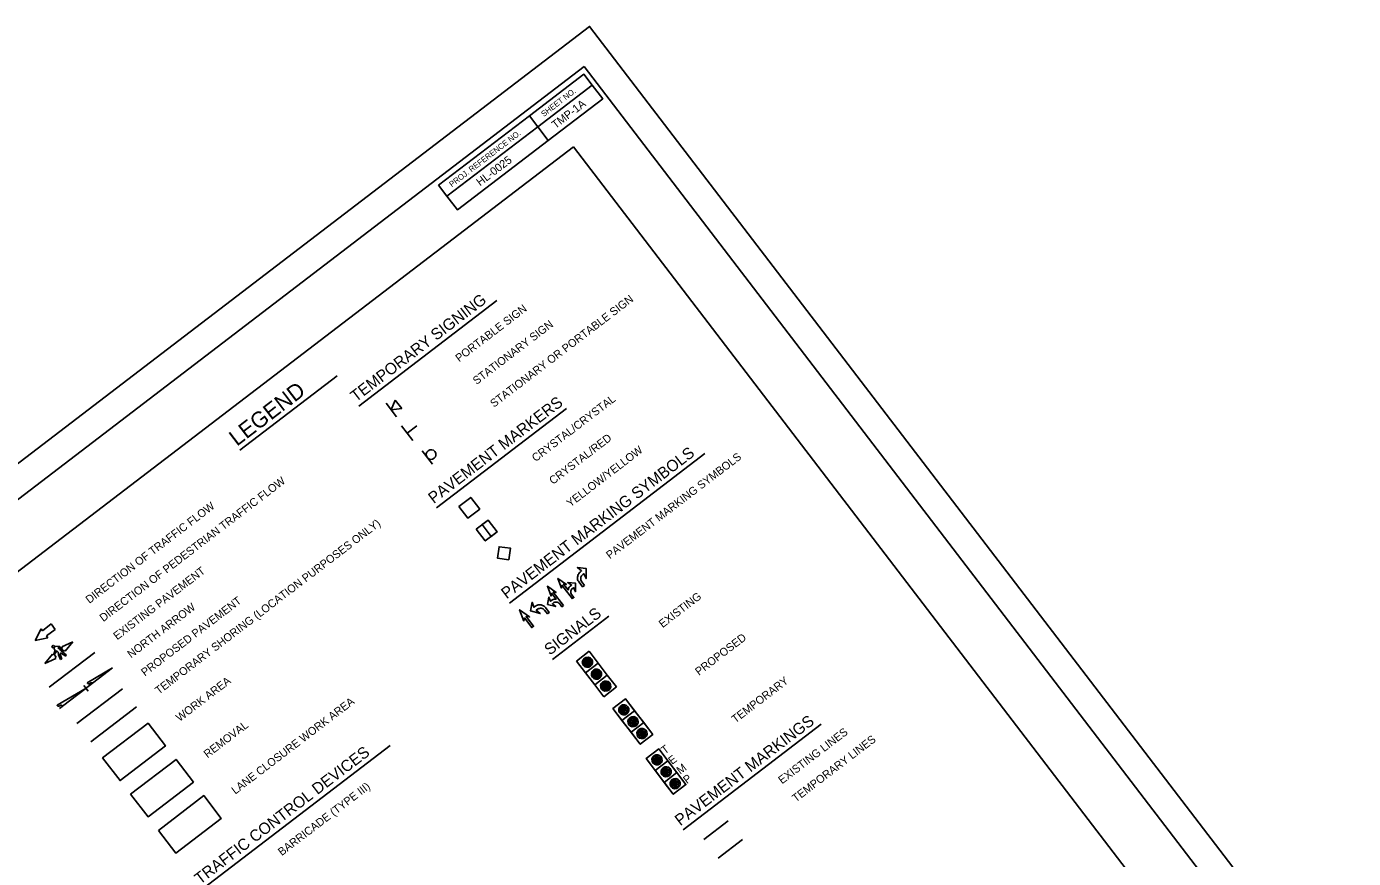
# Model space of a CAD drawing. Extents: x -642 to 2005, y -4412 to 1950.
# Drawn here: x 844 to 2005, y 1222 to 1950 of the extents above; entities that cross this region are included whole.
import ezdxf

# ---------------------------------------------------------------- set-up
doc = ezdxf.new("R2010")
doc.units = 0
for name, color, linetype in [('DEV BORDER CELL', 7, 'Continuous'), ('Gray Area Fill Shapes', 7, 'Continuous'), ('Scratch_Level_0', 7, 'Continuous'), ('Sheet Plot Border Outside CELL', 7, 'Continuous')]:
    doc.layers.add(name, color=color, linetype=linetype)

msp = doc.modelspace()

# ---------------------------------------------------------------- linework, layer by layer
at = {"layer": 'DEV BORDER CELL'}
for p, q in [((1291, 1861.8), (1338.6, 1898.3)), ((1134.4, 1617.4), (1255.3, 1709.9)), ((1030.3, 1578.7), (1115.6, 1643.9)), ((1158.4, 1619.9), (1167.4, 1608.1)), ((1162.8, 1614.1), (1166.4, 1622.7)), ((1172, 1615.3), (1162.8, 1614.1)), ((1166.4, 1622.7), (1172, 1615.3)), ((1202.5, 1528.4), (1316.2, 1615.4)), ((1171.9, 1600.2), (1181.8, 1587.3)), ((1176.9, 1593.7), (1185.2, 1600.1)), ((1189.8, 1578.3), (1198.9, 1566.6)), ((1266.2, 1445), (1437.2, 1575.8)), ((1303.9, 1395.7), (1353.3, 1433.5)), ((856.6, 1422.4), (851.3, 1412.2)), ((857.8, 1420.8), (856.6, 1422.4)), ((865.4, 1426.7), (857.8, 1420.8)), ((861.3, 1416.2), (868.9, 1422)), ((862.5, 1414.6), (861.3, 1416.2)), ((868.9, 1422), (865.4, 1426.7)), ((851.3, 1412.2), (862.5, 1414.6)), ((869.5, 1407.1), (872.4, 1407.4)), ((872, 1406.3), (871.3, 1406)), ((873.9, 1404.2), (872, 1406.3)), ((872.4, 1407.4), (874.5, 1404.7)), ((874.5, 1404.7), (873.9, 1404.2)), ((875.2, 1405.9), (874.5, 1405.3)), ((874.5, 1405.3), (876.2, 1403)), ((884.3, 1411), (874.6, 1406.6)), ((874.6, 1406.6), (875.2, 1405.9)), ((877.6, 1402.8), (884.3, 1411)), ((866.5, 1400.4), (859.7, 1392.2)), ((859.7, 1392.2), (869.4, 1396.5)), ((863.6, 1371.3), (903.5, 1401.8)), ((867.1, 1399.6), (866.5, 1400.4)), ((867.8, 1400.2), (867.1, 1399.6)), ((867.8, 1400.6), (868.8, 1403.4)), ((868.4, 1400.4), (867.8, 1400.6)), ((869.6, 1397.9), (867.8, 1400.2)), ((868.8, 1403.4), (868.3, 1404.3)), ((869.8, 1402.4), (868.4, 1400.4)), ((868.8, 1397.3), (869.6, 1397.9)), ((869.4, 1396.5), (868.8, 1397.3)), ((870, 1403.4), (869.8, 1402.4)), ((871.8, 1399.6), (871.4, 1402.1)), ((873.4, 1395.7), (871.8, 1399.6)), ((873.4, 1401.4), (873.3, 1400)), ((873.3, 1400), (874.7, 1396.2)), ((878.2, 1398.5), (873.4, 1401.4)), ((874.7, 1396.2), (873.4, 1395.7)), ((874.2, 1403.1), (878.5, 1399.6)), ((876.2, 1403), (877, 1403.6)), ((877, 1403.6), (877.6, 1402.8)), ((878.5, 1399.6), (878.2, 1398.5)), ((1324.9, 1394.3), (1335.9, 1402.8)), ((1332.8, 1383.9), (1324.9, 1394.3)), ((1330, 1393), (1330.3, 1394.7)), ((1330, 1393.6), (1338.8, 1392.4)), ((1330.2, 1394.5), (1338.9, 1393.4)), ((1330.6, 1395.5), (1338.8, 1394.5)), ((1330.7, 1390.8), (1331.5, 1396.6)), ((1331.4, 1396.4), (1338.3, 1395.5)), ((1331.6, 1389.8), (1332.6, 1397.3)), ((1332.6, 1389.2), (1333.7, 1397.6)), ((1332.6, 1397.3), (1337.4, 1396.7)), ((1333.5, 1388.9), (1334.7, 1397.7)), ((1334.5, 1388.8), (1335.7, 1397.5)), ((1335.6, 1388.9), (1336.7, 1397.1)), ((1335.9, 1402.8), (1343.9, 1392.4)), ((1336.6, 1389.4), (1337.6, 1396.5)), ((1337.8, 1390.3), (1338.4, 1395.3)), ((872.6, 1352.7), (919.1, 1388.2)), ((896.9, 1375.2), (919.1, 1388.2)), ((919.1, 1388.2), (901.4, 1374.8)), ((1330.1, 1392.5), (1338.5, 1391.4)), ((1330.4, 1391.5), (1338, 1390.5)), ((1331, 1390.4), (1337, 1389.6)), ((1332.7, 1389.2), (1335.1, 1388.9)), ((1332.8, 1383.9), (1343.9, 1392.4)), ((1340.8, 1373.5), (1332.8, 1383.9)), ((1338, 1383.4), (1346.8, 1382.2)), ((1338, 1382.4), (1346.6, 1381.3)), ((1338.1, 1381.9), (1338.5, 1384.9)), ((1338.2, 1381.3), (1346.1, 1380.3)), ((1338.3, 1384.4), (1346.9, 1383.2)), ((1338.7, 1385.3), (1346.7, 1384.3)), ((1338.9, 1380.2), (1339.7, 1386.3)), ((1339.5, 1386.2), (1346.1, 1385.4)), ((1339.8, 1379.3), (1340.8, 1387)), ((1340.7, 1378.7), (1341.9, 1387.3)), ((1351.8, 1382), (1340.8, 1373.5)), ((1341, 1387), (1345, 1386.5)), ((1341.7, 1378.5), (1342.9, 1387.3)), ((1342.7, 1378.4), (1343.9, 1387.1)), ((1343.7, 1378.6), (1344.8, 1386.6)), ((1343.9, 1392.4), (1351.8, 1382)), ((1344.8, 1379.1), (1345.7, 1385.9)), ((1345.9, 1380.1), (1346.6, 1384.6)), ((1351.8, 1382), (1359.8, 1371.6)), ((895.9, 1370.5), (870.5, 1355.6)), ((875.4, 1354.8), (895.9, 1370.5)), ((887.9, 1339.5), (927.8, 1370)), ((894, 1373), (897.8, 1368)), ((1338.8, 1380.2), (1345.2, 1379.4)), ((1340.1, 1379.1), (1343.7, 1378.6)), ((1348.8, 1363.1), (1340.8, 1373.5)), ((1346, 1373.1), (1354.8, 1372)), ((1346, 1372.1), (1354.6, 1371)), ((1346.1, 1371.1), (1354.1, 1370.1)), ((1346.3, 1374.1), (1354.8, 1373)), ((1346.6, 1370.1), (1347.3, 1375.6)), ((1346.7, 1370), (1353.4, 1369.1)), ((1346.8, 1375), (1354.6, 1374)), ((1347.4, 1369.1), (1348.4, 1376.4)), ((1347.7, 1375.9), (1354, 1375.1)), ((1348.4, 1368.5), (1349.5, 1376.8)), ((1359.8, 1371.6), (1348.8, 1363.1)), ((1349.3, 1368.1), (1350.5, 1376.9)), ((1349.3, 1376.8), (1352.6, 1376.3)), ((1350.3, 1368), (1351.5, 1376.8)), ((1351.4, 1368.1), (1352.5, 1376.4)), ((1352.4, 1368.5), (1353.4, 1375.8)), ((1353.5, 1369.3), (1354.3, 1374.7)), ((1347.7, 1368.9), (1352, 1368.3)), ((900, 1323.6), (939.9, 1354.1)), ((1370.5, 1350.4), (1361.9, 1351.5)), ((1370.7, 1351.9), (1362.1, 1353)), ((1369.8, 1349), (1362.2, 1349.9)), ((1362.7, 1349), (1363.6, 1355.1)), ((1370.4, 1353.4), (1362.9, 1354.4)), ((1368.2, 1347.6), (1363.4, 1348.3)), ((1364.1, 1347.8), (1365.2, 1355.9)), ((1369, 1355.1), (1364.6, 1355.7)), ((1365.5, 1347.3), (1366.7, 1356)), ((1367, 1347.3), (1368.2, 1355.6)), ((1368.6, 1347.9), (1369.6, 1354.6)), ((1370.5, 1350.3), (1370.7, 1352.1)), ((1378.5, 1340), (1369.9, 1341.1)), ((1378.7, 1341.5), (1370.1, 1342.6)), ((1377.8, 1338.5), (1370.2, 1339.5)), ((1370.7, 1338.6), (1371.5, 1344.7)), ((1378.3, 1343), (1370.8, 1344)), ((1376.2, 1337.2), (1371.4, 1337.9)), ((1372.1, 1337.4), (1373.1, 1345.5)), ((1377, 1344.7), (1372.6, 1345.3)), ((1373.5, 1336.8), (1374.7, 1345.6)), ((1375, 1336.9), (1376.2, 1345.2)), ((1376.6, 1337.5), (1377.5, 1344.2)), ((1378.5, 1339.9), (1378.7, 1341.6)), ((1380, 1327), (1381.1, 1335.1)), ((1385, 1334.3), (1380.6, 1334.9)), ((1381.4, 1326.4), (1382.7, 1335.2)), ((1418.1, 1246.5), (1539, 1338.9)), ((1386.5, 1329.6), (1377.8, 1330.7)), ((1386.7, 1331.1), (1378, 1332.2)), ((1385.7, 1328.1), (1378.1, 1329.1)), ((1378.6, 1328.2), (1379.5, 1334.2)), ((1386.3, 1332.6), (1378.8, 1333.6)), ((1384.1, 1326.8), (1379.3, 1327.5)), ((1383, 1326.5), (1384.1, 1334.8)), ((1384.5, 1327.1), (1385.5, 1333.8)), ((1386.4, 1329.5), (1386.7, 1331.2)), ((998.1, 1195.3), (1161.9, 1320.5)), ((1393.1, 1304), (1394.2, 1312.1)), ((1394.5, 1303.5), (1395.7, 1312.2)), ((1396, 1303.5), (1397.2, 1311.8)), ((1399.5, 1306.6), (1390.9, 1307.7)), ((1399.7, 1308.1), (1391.1, 1309.2)), ((1398.8, 1305.2), (1391.2, 1306.1)), ((1391.7, 1305.2), (1392.6, 1311.3)), ((1399.4, 1309.6), (1391.9, 1310.6)), ((1397.2, 1303.8), (1392.4, 1304.5)), ((1397.6, 1304.1), (1398.6, 1310.8)), ((1399.7, 1294.8), (1400.5, 1300.9)), ((1407.3, 1299.2), (1399.8, 1300.2)), ((1401.1, 1293.6), (1402.1, 1301.7)), ((1402.5, 1293.1), (1403.7, 1301.8)), ((1404, 1293.1), (1405.2, 1301.4)), ((1405.6, 1293.7), (1406.5, 1300.4)), ((1407.5, 1296.2), (1398.9, 1297.3)), ((1407.7, 1297.7), (1399, 1298.8)), ((1406.8, 1294.8), (1399.2, 1295.7)), ((1405.2, 1293.4), (1400.4, 1294.1)), ((1415.7, 1287.3), (1407, 1288.4)), ((1407.6, 1284.4), (1408.5, 1290.5)), ((1415.3, 1288.8), (1407.8, 1289.8)), ((1409, 1283.2), (1410.1, 1291.3)), ((1410.4, 1282.6), (1411.6, 1291.4)), ((1411.9, 1282.7), (1413.1, 1291)), ((1413.5, 1283.3), (1414.5, 1290)), ((1415.5, 1285.8), (1406.8, 1286.9)), ((1414.7, 1284.3), (1407.1, 1285.3)), ((1413.1, 1283), (1408.3, 1283.7)), ((998.9, 1276.5), (959.2, 1246.1)), ((1014.1, 1256.6), (998.9, 1276.5)), ((974.4, 1226.2), (1014.1, 1256.6)), ((1436.2, 1238.2), (1457.5, 1254.4)), ((959.2, 1246.1), (974.4, 1226.2)), ((1448.8, 1221.7), (1470.1, 1238))]:
    msp.add_line(p, q, dxfattribs=at)
for points in [[(1331.7, 1914.5), (140.1, 1003.4), (777.9, 169.3), (1969.5, 1080.4)], [(1291, 1861.8), (1338.6, 1898.3), (1331.4, 1907.8), (1283.7, 1871.4)], [(1291, 1861.8), (1338.6, 1898.3), (1347.8, 1886.4), (1300.1, 1849.9)], [(1204.3, 1810.6), (1283.7, 1871.4), (1291, 1861.8), (1211.5, 1801.1)], [(1291, 1861.8), (1211.5, 1801.1), (1220.7, 1789.2), (1300.1, 1849.9)], [(1242.4, 1513.7), (1247.5, 1517.6), (1255.4, 1507.3), (1250.3, 1503.4)], [(1265.8, 1483), (1267.2, 1493), (1257.2, 1494.3), (1255.9, 1484.3)], [(1265.8, 1483), (1267.2, 1493), (1257.2, 1494.3), (1255.9, 1484.3)], [(1265.8, 1483), (1255.9, 1484.3), (1257.2, 1494.3), (1267.2, 1493)], [(1331.8, 1460.5), (1330.2, 1459.3), (1327.1, 1463.4), (1326.6, 1464.2), (1326.2, 1464.9), (1325.9, 1465.6), (1325.8, 1466.4), (1325.8, 1467), (1325.8, 1467.8), (1326, 1468.5), (1326.1, 1469.2), (1326.5, 1470.1), (1326.8, 1470.7), (1327.3, 1471.4), (1328.2, 1472.2), (1329.4, 1473.2), (1325.7, 1476), (1333.3, 1475.3), (1333.3, 1466.5), (1331.4, 1470.7), (1330.3, 1469.9), (1329.8, 1469.4), (1329.3, 1468.8), (1329, 1468.3), (1328.7, 1467.6), (1328.6, 1467), (1328.6, 1466.1), (1328.7, 1465.3), (1329, 1464.5), (1329.5, 1463.6)], [(1321.3, 1448.8), (1312.2, 1460.6), (1311.8, 1458.1), (1308.6, 1466.6), (1316.1, 1461.4), (1313.6, 1461.6), (1317.5, 1456.5), (1317.8, 1457.4), (1318, 1458.1), (1318.5, 1458.8), (1318.9, 1459.3), (1319.4, 1459.8), (1320.6, 1460.7), (1317.3, 1463), (1323.9, 1462.5), (1323.9, 1454.9), (1322.2, 1458.5), (1321.4, 1457.8), (1320.9, 1457.4), (1320.4, 1456.9), (1320.2, 1456.3), (1319.9, 1455.7), (1319.8, 1454.8), (1319.9, 1454), (1320.2, 1453.2), (1320.6, 1452.4), (1322.6, 1449.8)], [(1313.5, 1442.8), (1304.5, 1454.6), (1307, 1454.4), (1299.5, 1459.7), (1302.7, 1451.1), (1303.1, 1453.6), (1307, 1448.4), (1306, 1448.5), (1305.3, 1448.4), (1304.5, 1448.1), (1304, 1447.9), (1303.3, 1447.5), (1302.2, 1446.6), (1300.7, 1450.3), (1299.6, 1443.9), (1306.8, 1441.9), (1303.8, 1444.4), (1304.7, 1445.1), (1305.2, 1445.5), (1305.9, 1445.7), (1306.5, 1445.8), (1307.2, 1445.9), (1308, 1445.8), (1308.8, 1445.5), (1309.5, 1445), (1310.2, 1444.4), (1312.1, 1441.8)], [(1299.4, 1435.7), (1301, 1436.9), (1297.8, 1441), (1297.2, 1441.8), (1296.7, 1442.3), (1296, 1442.7), (1295.3, 1443), (1294.7, 1443.2), (1293.9, 1443.4), (1293.2, 1443.5), (1292.4, 1443.5), (1291.5, 1443.4), (1290.9, 1443.2), (1290, 1442.9), (1289, 1442.3), (1287.7, 1441.3), (1286.1, 1445.7), (1284.7, 1438.1), (1293.2, 1435.8), (1289.7, 1438.8), (1290.7, 1439.6), (1291.3, 1440), (1292, 1440.3), (1292.6, 1440.4), (1293.4, 1440.5), (1294, 1440.5), (1294.8, 1440.3), (1295.6, 1439.9), (1296.3, 1439.5), (1297, 1438.8)], [(1278.8, 1429.1), (1279.3, 1432), (1285.7, 1423.5), (1287.3, 1424.7), (1280.8, 1433.2), (1283.8, 1432.9), (1275.1, 1439.1)], [(1356.7, 1352.7), (1367.8, 1361.2), (1391.6, 1330), (1380.6, 1321.5)], [(1364.7, 1342.3), (1375.7, 1350.8), (1367.8, 1361.2), (1356.7, 1352.7)], [(1372.6, 1331.9), (1383.7, 1340.4), (1375.7, 1350.8), (1364.7, 1342.3)], [(910.4, 1309.5), (950.1, 1339.9), (965.3, 1320), (925.6, 1289.6)], [(1380.6, 1321.5), (1391.6, 1330), (1383.7, 1340.4), (1372.6, 1331.9)], [(1385.7, 1308.9), (1396.8, 1317.4), (1420.6, 1286.2), (1409.6, 1277.7)], [(1393.7, 1298.5), (1404.7, 1307), (1396.8, 1317.4), (1385.7, 1308.9)], [(934.9, 1277.9), (974.6, 1308.2), (989.8, 1288.4), (950.1, 1258)], [(934.9, 1277.9), (974.6, 1308.2), (989.8, 1288.4), (950.1, 1258)], [(934.9, 1277.9), (974.6, 1308.2), (989.8, 1288.4), (950.1, 1258)], [(1401.6, 1288.1), (1412.7, 1296.6), (1404.7, 1307), (1393.7, 1298.5)], [(1409.6, 1277.7), (1420.6, 1286.2), (1412.7, 1296.6), (1401.6, 1288.1)], [(959.2, 1246.1), (998.9, 1276.5), (1014.1, 1256.6), (974.4, 1226.2)]]:
    msp.add_lwpolyline(points, close=True, dxfattribs=at)
for points in [[(1222, 1529.6), (1232.4, 1537.5), (1240.3, 1527.2), (1229.9, 1519.3), (1222, 1529.6)], [(1237.2, 1509.7), (1247.5, 1517.6), (1255.4, 1507.3), (1245.1, 1499.4), (1237.2, 1509.7)]]:
    msp.add_lwpolyline(points, dxfattribs=at)
msp.add_circle((867.2, 1406.9), 1.11, dxfattribs=at)
for centre, radius, start, end in [((1197.7, 1575), 4.28, 220.3871, 217.2203), ((871.2, 1405.8), 3.22, 177.5907, 207.9785), ((868.8, 1405.9), 0.84, 134.3035, 177.5907), ((869.7, 1404.9), 2.19, 96.5687, 134.3035), ((867.1, 1398.8), 8.29, 31.0586, 59.6568), ((867.1, 1398.8), 5.41, 37.711, 57.7902)]:
    msp.add_arc(centre, radius, start, end, dxfattribs=at)
for centre, major_axis in [((1334.5, 1393.2), (3.55, 2.72)), ((1342.4, 1382.8), (3.55, 2.72)), ((1350.4, 1372.4), (3.55, 2.72)), ((1366.3, 1351.6), (3.55, 2.71)), ((1374.3, 1341.2), (3.55, 2.71)), ((1382.2, 1330.8), (3.55, 2.71)), ((1395.3, 1307.8), (3.55, 2.71)), ((1403.3, 1297.4), (3.55, 2.71)), ((1411.2, 1287), (3.55, 2.71))]:
    msp.add_ellipse(centre, major_axis=major_axis, ratio=0.992944, dxfattribs=at)
for points in [[(901.4, 1374.7), (900.8, 1375.9), (897.9, 1373.7), (896.9, 1375.2)], [(870.5, 1355.6), (871.5, 1354.1), (874.4, 1356.2), (875.4, 1354.8)]]:
    msp.add_open_spline(points, degree=2, dxfattribs=at)
at = {"layer": 'Gray Area Fill Shapes'}
msp.add_lwpolyline([(925.6, 1289.6), (965.3, 1320), (950.1, 1339.9), (910.4, 1309.5)], close=True, dxfattribs=at)
at = {"layer": 'Scratch_Level_0'}
msp.add_lwpolyline([(1322.3, 1844.4), (210.2, 994), (787.3, 239.4), (1485.4, 773.2), (1413.6, 867.2), (1827.6, 1183.7)], close=True, dxfattribs=at)
at = {"layer": 'Sheet Plot Border Outside CELL'}
msp.add_lwpolyline([(663.6, 50.4), (2004.5, 1075.8), (1336.4, 1949.6), (-4.5, 924.2)], close=True, dxfattribs=at)

# ---------------------------------------------------------------- texts
at = {"layer": 'DEV BORDER CELL'}
for s, height, rotation, p in [('SHEET NO.', 5, 37.4045, (1296.3, 1870.3)), ('TMP-1A', 7, 37.404, (1306.5, 1859.8)), ('PROJ. REFERENCE NO.', 4.999, 37.4045, (1215.9, 1808.8)), ('HL-0025', 7, 37.404, (1240.6, 1809.6)), ('TEMPORARY SIGNING', 10, 37.4042, (1132, 1620.6)), ('PORTABLE SIGN', 7, 37.4042, (1222.3, 1655.6)), ('STATIONARY OR PORTABLE SIGN', 7, 37.4042, (1252.7, 1615.9)), ('STATIONARY SIGN', 7, 37.4042, (1237.5, 1635.8)), ('LEGEND', 14, 37.404, (1027.8, 1581.8)), ('PAVEMENT MARKERS', 10, 37.4042, (1200, 1531.6)), ('CRYSTAL/CRYSTAL', 7, 37.4042, (1289.1, 1568.3)), ('CRYSTAL/RED', 7, 37.4042, (1304.3, 1548.4)), ('PAVEMENT MARKING SYMBOLS', 10, 37.4042, (1263.8, 1448.2)), ('YELLOW/YELLOW', 7, 37.4042, (1319.5, 1528.6)), ('PAVEMENT MARKING SYMBOLS', 7, 37.4042, (1354.1, 1483.2)), ('DIRECTION OF PEDESTRIAN TRAFFIC FLOW', 7, 37.404, (911, 1428.3)), ('DIRECTION OF TRAFFIC FLOW', 7, 37.404, (898.8, 1444.2)), ('TEMPORARY SHORING (LOCATION PURPOSES ONLY)', 7, 37.404, (959.6, 1364.7)), ('EXISTING PAVEMENT', 7, 37.404, (923.1, 1412.4)), ('PROPOSED PAVEMENT', 7, 37.404, (947.4, 1380.6)), ('EXISTING', 7, 37.4045, (1400.2, 1423)), ('NORTH ARROW', 7, 37.404, (935.3, 1396.5)), ('SIGNALS', 10, 37.4042, (1301.5, 1398.9)), ('PROPOSED', 7, 37.4045, (1432, 1381.3)), ('WORK AREA', 7, 37.404, (977.8, 1340.9)), ('TEMPORARY ', 7, 37.4045, (1463.9, 1339.6)), ('LANE CLOSURE WORK AREA', 7, 37.404, (1026.4, 1277.3)), ('PAVEMENT MARKINGS', 10, 37.4042, (1415.7, 1249.6)), ('REMOVAL', 7, 37.404, (1002.1, 1309.1)), ('EXISTING LINES', 7, 37.4042, (1504.7, 1286.3)), ('TEMPORARY LINES', 7, 37.4042, (1516.8, 1270.4)), ('TRAFFIC CONTROL DEVICES', 10, 37.4042, (995.6, 1198.4)), ('T', 7, 37.404, (1402.2, 1312.4)), ('E', 7, 37.404, (1408.5, 1303.3)), ('M', 7, 37.404, (1415.7, 1294.8)), ('P', 7, 37.404, (1421.5, 1286.5)), ('BARRICADE (TYPE III)', 7, 37.4042, (1067.1, 1223.5))]:
    msp.add_text(s, height=height, rotation=rotation, dxfattribs=at).set_placement(p)

doc.saveas('drawing.dxf')
